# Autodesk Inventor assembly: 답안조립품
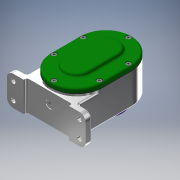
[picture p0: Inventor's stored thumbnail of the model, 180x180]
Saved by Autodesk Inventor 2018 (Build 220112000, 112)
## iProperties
Created: 2021-05
Part Number: 답안조립품
Material: 일반
Document SubType Name: Assembly
Designer: Admin
Author: Admin
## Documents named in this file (19)
- C:\Users\Admin\Desktop\710509V1007\답안조립품.iam
- C:\Users\Admin\Desktop\710509V1007\본체.ipt
- C:\Users\Admin\Desktop\710509V1007\부품\축 A.ipt
- C:\Users\Admin\Desktop\710509V1007\부품\축 B.ipt
- C:\Users\Admin\Desktop\710509V1007\부품\베어링 6001.ipt
- 베어링 6001.ipt
- C:\Users\Admin\Desktop\710509V1007\부품\베어링 6002.ipt
- 베어링 6002.ipt
- C:\Users\Admin\Desktop\710509V1007\부품\칼라.ipt
- C:\Users\Admin\Desktop\710509V1007\부품\키 5 x 5 x 12.ipt
- C:\Users\Admin\Desktop\710509V1007\부품\키 4 x 4 x 12.ipt
- C:\Users\Admin\Desktop\710509V1007\부품\스퍼기어 A.ipt
- C:\Users\Admin\Desktop\710509V1007\부품\스퍼기어 B.ipt
- C:\Users\Admin\Desktop\710509V1007\부품\개스킷 A.ipt
- C:\Users\Admin\Desktop\710509V1007\부품\개스킷 B.ipt
- C:\Users\Admin\Desktop\710509V1007\부품\커버 A.ipt
- C:\Users\Admin\Desktop\710509V1007\부품\커버 B.ipt
- C:\Users\Admin\Desktop\710509V1007\부품\오일 실 12 22 7.ipt
- C:\Users\Admin\Desktop\710509V1007\부품\볼트 M4.ipt
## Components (2 placed, 2 different names)
1. 개스킷 A:1
2. 개스킷 B:1
